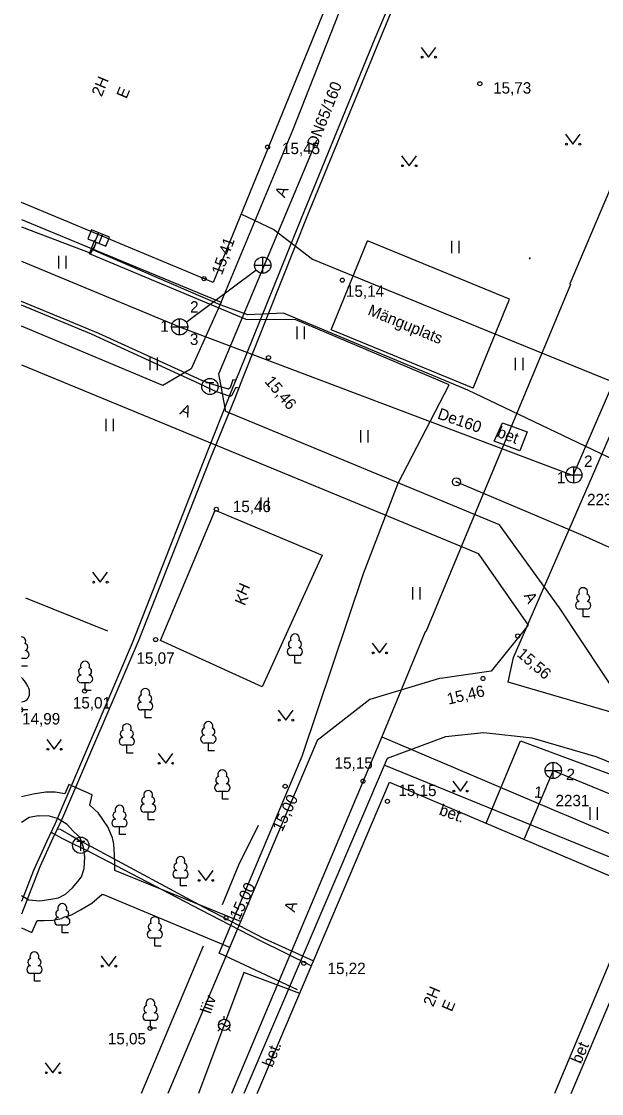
# Model space of a CAD drawing. Extents: x 713497 to 713863, y 6590062 to 6590327.
# Drawn here: x 713496.9 to 713532.5, y 6590062.3 to 6590128.2 of the extents above; entities that cross this region are included whole.
import ezdxf

# ---------------------------------------------------------------- set-up
doc = ezdxf.new("R2010")
doc.units = 0
for name, color, linetype in [('HALJASTUS', 7, 'Continuous'), ('HOONE', 7, 'Continuous'), ('HOONEDET', 7, 'Continuous'), ('KKAEV', 7, 'Continuous'), ('KORGUS', 7, 'Continuous'), ('KTRASS', 7, 'Continuous'), ('MPKAABEL', 7, 'Continuous'), ('POST', 7, 'Continuous'), ('PUU', 7, 'Continuous'), ('RAJATIS', 7, 'Continuous'), ('SIKAEV', 7, 'Continuous'), ('SITRASS', 7, 'Continuous'), ('TEE', 7, 'Continuous'), ('TKAEV', 7, 'Continuous'), ('TORU NR', 7, 'Continuous'), ('TTRASS', 7, 'Continuous'), ('VTRASS', 7, 'Continuous'), ('По умолчанию', 7, 'Continuous'), ('Слой 1', 7, 'Continuous')]:
    doc.layers.add(name, color=color, linetype=linetype)

msp = doc.modelspace()

# ---------------------------------------------------------------- linework, layer by layer
at = {"layer": 'HALJASTUS'}
for p, q in [((713521.427, 6590126.597), (713521.89, 6590125.99)), ((713521.89, 6590125.99), (713522.336, 6590126.597)), ((713530.297, 6590121.257), (713530.76, 6590120.65)), ((713530.76, 6590120.65), (713531.206, 6590121.257)), ((713520.227, 6590119.927), (713520.69, 6590119.32)), ((713520.69, 6590119.32), (713521.136, 6590119.927)), ((713515.892, 6590109.239), (713518.13, 6590114.698)), ((713526.87, 6590111.116), (713518.13, 6590114.698)), ((713523.303, 6590114.703), (713523.303, 6590113.941)), ((713523.758, 6590114.703), (713523.758, 6590113.941)), ((713499.135, 6590113.775), (713499.135, 6590113.014)), ((713499.59, 6590113.775), (713499.59, 6590113.014)), ((713524.632, 6590105.656), (713526.87, 6590111.116)), ((713513.782, 6590109.432), (713513.782, 6590108.671)), ((713514.237, 6590109.432), (713514.237, 6590108.671)), ((713524.632, 6590105.656), (713515.892, 6590109.239)), ((713504.75, 6590107.529), (713504.75, 6590106.768)), ((713505.205, 6590107.529), (713505.205, 6590106.768)), ((713527.217, 6590107.518), (713527.217, 6590106.757)), ((713527.672, 6590107.518), (713527.672, 6590106.757)), ((713502.049, 6590103.766), (713502.049, 6590103.005)), ((713502.504, 6590103.766), (713502.504, 6590103.005)), ((713517.696, 6590103.077), (713517.696, 6590102.316)), ((713518.151, 6590103.077), (713518.151, 6590102.316)), ((713511.57, 6590098.935), (713511.57, 6590098.174)), ((713512.025, 6590098.935), (713512.025, 6590098.174)), ((713501.237, 6590094.337), (713501.7, 6590093.73)), ((713501.7, 6590093.73), (713502.146, 6590094.337)), ((713520.895, 6590093.421), (713520.895, 6590092.66)), ((713521.35, 6590093.421), (713521.35, 6590092.66)), ((713518.417, 6590089.987), (713518.88, 6590089.38)), ((713518.88, 6590089.38), (713519.326, 6590089.987)), ((713512.647, 6590085.857), (713513.11, 6590085.25)), ((713513.11, 6590085.25), (713513.556, 6590085.857)), ((713498.417, 6590084.067), (713498.88, 6590083.46)), ((713498.88, 6590083.46), (713499.326, 6590084.067)), ((713505.267, 6590083.207), (713505.73, 6590082.6)), ((713505.73, 6590082.6), (713506.176, 6590083.207)), ((713523.377, 6590081.497), (713523.84, 6590080.89)), ((713523.84, 6590080.89), (713524.286, 6590081.497)), ((713531.803, 6590079.894), (713531.803, 6590079.133)), ((713532.258, 6590079.894), (713532.258, 6590079.133)), ((713507.727, 6590076.007), (713508.19, 6590075.4)), ((713508.19, 6590075.4), (713508.636, 6590076.007)), ((713501.767, 6590070.737), (713502.23, 6590070.13)), ((713502.23, 6590070.13), (713502.676, 6590070.737)), ((713498.327, 6590064.187), (713498.79, 6590063.58)), ((713498.79, 6590063.58), (713499.236, 6590064.187))]:
    msp.add_line(p, q, dxfattribs=at)
for points in [[(713502.18, 6590090.72), (713497.13, 6590092.75)], [(713511.42, 6590078.77), (713510.2, 6590076.33), (713509.2, 6590073.9)], [(713508.03, 6590071.37), (713504.228, 6590062.302)]]:
    msp.add_lwpolyline(points, dxfattribs=at)
for centre in [(713521.489, 6590125.99), (713522.318, 6590125.99), (713530.359, 6590120.65), (713531.188, 6590120.65), (713520.289, 6590119.32), (713521.118, 6590119.32), (713501.299, 6590093.73), (713502.128, 6590093.73), (713518.479, 6590089.38), (713519.308, 6590089.38), (713512.709, 6590085.25), (713513.538, 6590085.25), (713498.479, 6590083.46), (713499.308, 6590083.46), (713505.329, 6590082.6), (713506.158, 6590082.6), (713523.439, 6590080.89), (713524.268, 6590080.89), (713507.789, 6590075.4), (713508.618, 6590075.4), (713501.829, 6590070.13), (713502.658, 6590070.13), (713498.389, 6590063.58), (713499.218, 6590063.58)]:
    msp.add_circle(centre, 0.055, dxfattribs=at)
at = {"layer": 'HOONE'}
for p, q in [((713509.32, 6590066.87), (713509.32, 6590067.067)), ((713508.97, 6590066.518), (713509.181, 6590066.624)), ((713509.181, 6590066.624), (713509.459, 6590066.416)), ((713509.459, 6590066.416), (713509.67, 6590066.522)), ((713509.073, 6590066.273), (713508.933, 6590066.133)), ((713509.567, 6590066.273), (713509.707, 6590066.133))]:
    msp.add_line(p, q, dxfattribs=at)
for points in [[(713496.861, 6590174.047), (713502.16, 6590187.13), (713514.75, 6590181.98), (713510.98, 6590172.53), (713523.55, 6590167.23), (713525.32, 6590171.2), (713531.72, 6590168.66), (713508.647, 6590112.152)], [(713508.647, 6590112.152), (713496.861, 6590117.059)], [(713505.409, 6590090.144), (713508.778, 6590098.156), (713515.348, 6590095.393), (713511.649, 6590087.294), (713505.409, 6590090.144)], [(713511.353, 6590062.302), (713519.48, 6590081.443)], [(713519.48, 6590081.443), (713534.925, 6590074.886)], [(713534.925, 6590074.886), (713529.622, 6590062.302)], [(713513.966, 6590068.455), (713510.53, 6590069.75), (713507.737, 6590062.302)]]:
    msp.add_lwpolyline(points, dxfattribs=at)
msp.add_circle((713509.32, 6590066.52), 0.35, dxfattribs=at)
at = {"layer": 'HOONEDET'}
for points in [[(713496.861, 6590116.025), (713509.142, 6590110.933), (713513.543, 6590121.504), (713522.13, 6590143.33), (713524.66, 6590149.46), (713528.88, 6590159.51)], [(713530.649, 6590062.302), (713536.256, 6590075.51), (713519.161, 6590082.484)]]:
    msp.add_lwpolyline(points, dxfattribs=at)
at = {"layer": 'KKAEV'}
for p, q in [((713511.192, 6590113.21), (713512.192, 6590113.21)), ((713511.692, 6590112.71), (713511.692, 6590113.71)), ((713506.585, 6590108.92), (713506.585, 6590109.92)), ((713506.085, 6590109.42), (713507.085, 6590109.42)), ((713530.817, 6590099.818), (713530.817, 6590100.818)), ((713530.317, 6590100.318), (713531.317, 6590100.318)), ((713529.55, 6590081.656), (713529.55, 6590082.656)), ((713529.05, 6590082.156), (713530.05, 6590082.156))]:
    msp.add_line(p, q, dxfattribs=at)
for centre in [(713511.692, 6590113.21), (713506.585, 6590109.42), (713530.817, 6590100.318), (713529.55, 6590082.156)]:
    msp.add_circle(centre, 0.5, dxfattribs=at)
at = {"layer": 'KORGUS'}
for centre in [(713525.04, 6590124.36), (713511.99, 6590120.47), (713508.09, 6590112.38), (713516.58, 6590112.29), (713512.05, 6590107.53), (713508.84, 6590098.21), (713505.11, 6590090.2), (713527.37, 6590090.42), (713525.23, 6590087.81), (713500.74, 6590087.04), (713517.86, 6590081.5), (713513.07, 6590081.19), (713519.36, 6590080.26), (713509.43, 6590073.1), (713514.22, 6590070.3), (713504.77, 6590066.31)]:
    msp.add_circle(centre, 0.125, dxfattribs=at)
msp.add_arc((713496.84, 6590085.88), 0.125, 279.81452, 80.18548, dxfattribs=at)
at = {"layer": 'KTRASS'}
for p, q in [((713530.784, 6590100.288), (713536.778, 6590114.202)), ((713496.861, 6590113.464), (713506.585, 6590109.42)), ((713506.99, 6590109.712), (713511.272, 6590112.906)), ((713506.585, 6590109.42), (713530.784, 6590100.288))]:
    msp.add_line(p, q, dxfattribs=at)
for points in [[(713529.55, 6590082.156), (713527.773, 6590077.948)], [(713529.55, 6590082.156), (713542.997, 6590076.628)]]:
    msp.add_lwpolyline(points, dxfattribs=at)
at = {"layer": 'MPKAABEL'}
for points in [[(713496.861, 6590115.562), (713501.13, 6590113.94), (713501.472, 6590114.611)], [(713513.833, 6590068.67), (713509.018, 6590070.924), (713514.127, 6590083.042), (713517.884, 6590094.268), (713520.016, 6590099.81), (713523.148, 6590105.848), (713513.719, 6590109.842), (713510.668, 6590109.872), (713501.048, 6590113.897), (713501.37, 6590114.768)], [(713547.08, 6590094.66), (713531.975, 6590101.853), (713524.296, 6590105.519), (713512.967, 6590110.257), (713510.774, 6590110.16), (713509.074, 6590110.777), (713501.28, 6590114.132), (713501.453, 6590114.618)], [(713523.601, 6590099.894), (713531.341, 6590096.625), (713548.16, 6590089.06), (713554.53, 6590086.83), (713553.22, 6590083.602)]]:
    msp.add_lwpolyline(points, dxfattribs=at)
at = {"layer": 'POST'}
for p, q in [((713501.172, 6590115.383), (713500.942, 6590114.832)), ((713502.275, 6590114.922), (713501.172, 6590115.383)), ((713501.598, 6590115.205), (713501.368, 6590114.654)), ((713500.942, 6590114.832), (713502.044, 6590114.371)), ((713501.849, 6590115.1), (713501.619, 6590114.549)), ((713502.044, 6590114.371), (713502.275, 6590114.922))]:
    msp.add_line(p, q, dxfattribs=at)
for radius in [0.25, 0.0234]:
    msp.add_circle((713523.601, 6590099.894), radius, dxfattribs=at)
at = {"layer": 'PUU'}
for p, q in [((713531.63, 6590092.065), (713531.15, 6590092.065)), ((713531.39, 6590091.59), (713531.39, 6590092.065)), ((713531.77, 6590091.59), (713531.39, 6590091.59)), ((713497.09, 6590089.045), (713496.861, 6590089.045)), ((713513.91, 6590089.225), (713513.43, 6590089.225)), ((713513.67, 6590088.75), (713513.67, 6590089.225)), ((713497.23, 6590088.57), (713496.861, 6590088.57)), ((713514.05, 6590088.75), (713513.67, 6590088.75)), ((713501.01, 6590087.545), (713500.53, 6590087.545)), ((713500.77, 6590087.07), (713500.77, 6590087.545)), ((713501.15, 6590087.07), (713500.77, 6590087.07)), ((713497.26, 6590085.88), (713496.86, 6590085.88)), ((713504.71, 6590085.875), (713504.23, 6590085.875)), ((713504.47, 6590085.4), (713504.47, 6590085.875)), ((713504.85, 6590085.4), (713504.47, 6590085.4)), ((713503.58, 6590083.705), (713503.1, 6590083.705)), ((713503.34, 6590083.23), (713503.34, 6590083.705)), ((713508.59, 6590083.845), (713508.11, 6590083.845)), ((713508.35, 6590083.37), (713508.35, 6590083.845)), ((713503.72, 6590083.23), (713503.34, 6590083.23)), ((713508.73, 6590083.37), (713508.35, 6590083.37)), ((713509.45, 6590080.865), (713508.97, 6590080.865)), ((713509.21, 6590080.39), (713509.21, 6590080.865)), ((713509.59, 6590080.39), (713509.21, 6590080.39)), ((713504.89, 6590079.605), (713504.41, 6590079.605)), ((713504.65, 6590079.13), (713504.65, 6590079.605)), ((713505.03, 6590079.13), (713504.65, 6590079.13)), ((713503.13, 6590078.695), (713502.65, 6590078.695)), ((713502.89, 6590078.22), (713502.89, 6590078.695)), ((713503.27, 6590078.22), (713502.89, 6590078.22)), ((713506.88, 6590075.545), (713506.4, 6590075.545)), ((713506.64, 6590075.07), (713506.64, 6590075.545)), ((713507.02, 6590075.07), (713506.64, 6590075.07)), ((713499.61, 6590072.655), (713499.13, 6590072.655)), ((713499.37, 6590072.18), (713499.37, 6590072.655)), ((713499.75, 6590072.18), (713499.37, 6590072.18)), ((713505.3, 6590071.845), (713504.82, 6590071.845)), ((713505.06, 6590071.37), (713505.06, 6590071.845)), ((713505.44, 6590071.37), (713505.06, 6590071.37)), ((713497.9, 6590069.685), (713497.42, 6590069.685)), ((713497.66, 6590069.21), (713497.66, 6590069.685)), ((713498.04, 6590069.21), (713497.66, 6590069.21)), ((713505.03, 6590066.795), (713504.55, 6590066.795)), ((713504.79, 6590066.32), (713504.79, 6590066.795)), ((713505.17, 6590066.32), (713504.79, 6590066.32))]:
    msp.add_line(p, q, dxfattribs=at)
msp.add_lwpolyline([(713497.36, 6590086.88), (713497.36, 6590087.03), (713497.35, 6590087.095), (713497.315, 6590087.225), (713497.255, 6590087.345), (713497.11, 6590087.58), (713496.95, 6590087.785), (713496.86, 6590087.88)], dxfattribs=at)
for centre, radius, start, end in [((713531.22, 6590092.763), 0.233, 109.02174, 253.14154), ((713531.39, 6590093.11), 0.277, 332.5799, 207.4201), ((713531.56, 6590092.763), 0.233, 286.85082, 70.98591), ((713531.153, 6590092.302), 0.238, 90.0016, 269.3953), ((713531.627, 6590092.302), 0.238, 270.6047, 89.9984), ((713496.85, 6590090.09), 0.277, 332.5799, 87.66023), ((713513.5, 6590089.923), 0.233, 109.02174, 253.14154), ((713513.67, 6590090.27), 0.277, 332.5799, 207.4201), ((713513.84, 6590089.923), 0.233, 286.85082, 70.98591), ((713497.02, 6590089.743), 0.233, 286.85082, 70.98591), ((713497.087, 6590089.282), 0.238, 270.6047, 89.9984), ((713513.433, 6590089.462), 0.238, 90.0016, 269.3953), ((713513.907, 6590089.462), 0.238, 270.6047, 89.9984), ((713500.77, 6590088.59), 0.277, 332.5799, 207.4201), ((713500.6, 6590088.243), 0.233, 109.02174, 253.14154), ((713500.94, 6590088.243), 0.233, 286.85082, 70.98591), ((713500.533, 6590087.782), 0.238, 90.0016, 269.3953), ((713501.007, 6590087.782), 0.238, 270.6047, 89.9984), ((713496.86, 6590086.88), 0.5, 270.14982, 0), ((713504.47, 6590086.92), 0.277, 332.5799, 207.4201), ((713504.233, 6590086.112), 0.238, 90.0016, 269.3953), ((713504.3, 6590086.573), 0.233, 109.02174, 253.14154), ((713504.64, 6590086.573), 0.233, 286.85082, 70.98591), ((713504.707, 6590086.112), 0.238, 270.6047, 89.9984), ((713503.34, 6590084.75), 0.277, 332.5799, 207.4201), ((713508.35, 6590084.89), 0.277, 332.5799, 207.4201), ((713503.17, 6590084.403), 0.233, 109.02174, 253.14154), ((713503.51, 6590084.403), 0.233, 286.85082, 70.98591), ((713508.113, 6590084.082), 0.238, 90.0016, 269.3953), ((713508.18, 6590084.543), 0.233, 109.02174, 253.14154), ((713508.52, 6590084.543), 0.233, 286.85082, 70.98591), ((713508.587, 6590084.082), 0.238, 270.6047, 89.9984), ((713503.103, 6590083.942), 0.238, 90.0016, 269.3953), ((713503.577, 6590083.942), 0.238, 270.6047, 89.9984), ((713509.04, 6590081.563), 0.233, 109.02174, 253.14154), ((713509.21, 6590081.91), 0.277, 332.5799, 207.4201), ((713509.38, 6590081.563), 0.233, 286.85082, 70.98591), ((713504.65, 6590080.65), 0.277, 332.5799, 207.4201), ((713508.973, 6590081.102), 0.238, 90.0016, 269.3953), ((713509.447, 6590081.102), 0.238, 270.6047, 89.9984), ((713504.48, 6590080.303), 0.233, 109.02174, 253.14154), ((713504.82, 6590080.303), 0.233, 286.85082, 70.98591), ((713502.72, 6590079.393), 0.233, 109.02174, 253.14154), ((713502.89, 6590079.74), 0.277, 332.5799, 207.4201), ((713503.06, 6590079.393), 0.233, 286.85082, 70.98591), ((713504.413, 6590079.842), 0.238, 90.0016, 269.3953), ((713504.887, 6590079.842), 0.238, 270.6047, 89.9984), ((713502.653, 6590078.932), 0.238, 90.0016, 269.3953), ((713503.127, 6590078.932), 0.238, 270.6047, 89.9984), ((713506.47, 6590076.243), 0.233, 109.02174, 253.14154), ((713506.64, 6590076.59), 0.277, 332.5799, 207.4201), ((713506.81, 6590076.243), 0.233, 286.85082, 70.98591), ((713506.403, 6590075.782), 0.238, 90.0016, 269.3953), ((713506.877, 6590075.782), 0.238, 270.6047, 89.9984), ((713499.37, 6590073.7), 0.277, 332.5799, 207.4201), ((713499.133, 6590072.892), 0.238, 90.0016, 269.3953), ((713499.2, 6590073.353), 0.233, 109.02174, 253.14154), ((713499.54, 6590073.353), 0.233, 286.85082, 70.98591), ((713499.607, 6590072.892), 0.238, 270.6047, 89.9984), ((713505.06, 6590072.89), 0.277, 332.5799, 207.4201), ((713504.89, 6590072.543), 0.233, 109.02174, 253.14154), ((713505.23, 6590072.543), 0.233, 286.85082, 70.98591), ((713504.823, 6590072.082), 0.238, 90.0016, 269.3953), ((713505.297, 6590072.082), 0.238, 270.6047, 89.9984), ((713497.49, 6590070.383), 0.233, 109.02174, 253.14154), ((713497.66, 6590070.73), 0.277, 332.5799, 207.4201), ((713497.83, 6590070.383), 0.233, 286.85082, 70.98591), ((713497.423, 6590069.922), 0.238, 90.0016, 269.3953), ((713497.897, 6590069.922), 0.238, 270.6047, 89.9984), ((713504.79, 6590067.84), 0.277, 332.5799, 207.4201), ((713504.553, 6590067.032), 0.238, 90.0016, 269.3953), ((713504.62, 6590067.493), 0.233, 109.02174, 253.14154), ((713504.96, 6590067.493), 0.233, 286.85082, 70.98591), ((713505.027, 6590067.032), 0.238, 270.6047, 89.9984)]:
    msp.add_arc(centre, radius, start, end, dxfattribs=at)
at = {"layer": 'SITRASS'}
for points in [[(713520.04, 6590168.71), (713520.66, 6590170.09), (713550.09, 6590157.93), (713545.56, 6590146.97), (713536.57, 6590126.19), (713530.579, 6590112.058), (713530.622, 6590112.032), (713525.41, 6590099.54), (713521.713, 6590090.677), (713521.682, 6590090.679), (713519.02, 6590084.22), (713509.781, 6590062.302)], [(713510.396, 6590116.353), (713512.37, 6590115.41), (713514.75, 6590113.57), (713524.96, 6590109.41), (713533.116, 6590106.09), (713533.111, 6590106.069), (713537.62, 6590104.22), (713562.8, 6590094.1)], [(713519.02, 6590084.22), (713530.144, 6590079.502), (713530.341, 6590079.419), (713556.815, 6590068.191), (713567.05, 6590063.85), (713570.898, 6590062.302)]]:
    msp.add_lwpolyline(points, dxfattribs=at)
at = {"layer": 'TEE'}
for points in [[(713583.68, 6590106.09), (713587.4, 6590104.64), (713589.78, 6590103.58), (713589.96, 6590103.4), (713590.01, 6590103.08), (713590.01, 6590102.71), (713590.01, 6590102.34), (713585.33, 6590092.09), (713584.97, 6590091.18), (713584.97, 6590090.9), (713584.78, 6590090.76), (713584.05, 6590090.35), (713578.15, 6590087.01), (713571.27, 6590082.98), (713561.885, 6590077.404), (713551.992, 6590081.16), (713545.288, 6590081.565), (713534.534, 6590085.605), (713533.935, 6590086.13), (713529.929, 6590092.161), (713526.251, 6590097.247), (713509.421, 6590104.216), (713508.991, 6590106.523), (713515.019, 6590120.888)], [(713509.142, 6590110.933), (713507.297, 6590106.834), (713505.551, 6590105.821), (713496.861, 6590109.452)], [(713496.861, 6590107.09), (713516.784, 6590098.872), (713524.413, 6590095.711), (713524.94, 6590095.483), (713528.01, 6590091.097), (713525.732, 6590088.265), (713522.754, 6590087.84), (713522.553, 6590087.811), (713518.27, 6590086.509), (713515.031, 6590084.009), (713505.853, 6590062.302)], [(713527.945, 6590102.96), (713527.502, 6590101.793), (713525.922, 6590102.392), (713526.439, 6590103.53), (713527.945, 6590102.96)], [(713542.421, 6590078.847), (713532.192, 6590082.989), (713528.263, 6590084.136), (713525.285, 6590084.466), (713522.922, 6590084.219), (713519.34, 6590082.903), (713510.537, 6590062.302)], [(713510.323, 6590072.874), (713502.61, 6590076.02), (713502.61, 6590076.37), (713502.58, 6590076.95), (713502.53, 6590077.62), (713502.46, 6590078.02), (713502.17, 6590078.69), (713501.59, 6590079.53), (713501.07, 6590080.02), (713501.21, 6590080.67), (713499.77, 6590081.29), (713499.52, 6590080.73), (713498.94, 6590080.83), (713498.36, 6590080.83), (713497.59, 6590080.71), (713496.861, 6590080.533)], [(713496.861, 6590074.472), (713497.31, 6590074.21), (713497.99, 6590074.14), (713498.66, 6590074.24), (713499.14, 6590074.33), (713499.56, 6590074.56), (713500, 6590074.94), (713500.33, 6590075.33), (713500.56, 6590075.63), (713500.72, 6590076.14), (713500.75, 6590076.84), (713500.68, 6590077.44), (713500.45, 6590078.06), (713500.07, 6590078.41), (713499.68, 6590078.83), (713499.07, 6590079.2), (713498.5, 6590079.37), (713497.94, 6590079.34), (713497.91, 6590079.37), (713497.34, 6590079.27), (713496.861, 6590078.968)], [(713496.861, 6590072.482), (713497.5, 6590072.2), (713497.82, 6590072.94), (713498.26, 6590072.94), (713498.78, 6590072.96), (713499.33, 6590073.06), (713499.47, 6590073.15), (713499.93, 6590073.28), (713500.49, 6590073.59), (713501.19, 6590074), (713501.81, 6590074.54), (713501.91, 6590074.54), (713509.659, 6590071.303)]]:
    msp.add_lwpolyline(points, dxfattribs=at)
at = {"layer": 'TKAEV'}
for p, q in [((713508.197, 6590106.004), (713508.697, 6590106.004)), ((713508.447, 6590105.404), (713508.447, 6590106.004)), ((713500.257, 6590077.812), (713500.757, 6590077.812)), ((713500.507, 6590077.212), (713500.507, 6590077.812))]:
    msp.add_line(p, q, dxfattribs=at)
for centre in [(713508.447, 6590105.754), (713500.507, 6590077.562)]:
    msp.add_circle(centre, 0.5, dxfattribs=at)
at = {"layer": 'TTRASS'}
for p, q in [((713501.609, 6590109.008), (713496.861, 6590110.975)), ((713501.167, 6590108.964), (713496.861, 6590110.755)), ((713508.081, 6590105.786), (713501.167, 6590108.964)), ((713507.908, 6590106.151), (713501.609, 6590109.008)), ((713508.62, 6590105.877), (713507.908, 6590106.151)), ((713509.854, 6590106.158), (713509.698, 6590105.669)), ((713509.96, 6590106.152), (713509.854, 6590106.158)), ((713510.033, 6590106.151), (713509.96, 6590106.152)), ((713508.749, 6590105.47), (713508.081, 6590105.786)), ((713509.583, 6590105.595), (713508.62, 6590105.877)), ((713509.683, 6590105.13), (713508.749, 6590105.47)), ((713509.698, 6590105.669), (713509.583, 6590105.595)), ((713510.027, 6590105.663), (713509.795, 6590105.192)), ((713510.113, 6590105.68), (713510.027, 6590105.663)), ((713510.205, 6590105.647), (713510.113, 6590105.68)), ((713509.795, 6590105.192), (713509.683, 6590105.13))]:
    msp.add_line(p, q, dxfattribs=at)
for points in [[(713536.934, 6590171.606), (713532.46, 6590160.453), (713527.91, 6590149.36), (713523.736, 6590139.265), (713523.274, 6590138.194), (713518.578, 6590127.143), (713514.065, 6590116.073), (713510.261, 6590106.689), (713509.805, 6590105.613), (713508.03, 6590101.103), (713503.677, 6590089.984), (713498.935, 6590078.894), (713498.423, 6590077.821), (713497.604, 6590076.002), (713496.861, 6590074.102)], [(713537.097, 6590171.235), (713532.58, 6590160.187), (713527.979, 6590149.094), (713524.066, 6590139.498), (713523.58, 6590138.439), (713518.986, 6590127.351), (713514.448, 6590116.279), (713510.455, 6590106.239), (713510.003, 6590105.074), (713508.449, 6590101.266), (713504.084, 6590090.191), (713499.316, 6590079.103), (713498.784, 6590077.994), (713497.983, 6590076.242), (713496.861, 6590073.337)], [(713498.679, 6590078.357), (713498.8, 6590078.299), (713499.379, 6590077.979), (713500.091, 6590077.632), (713500.783, 6590077.305), (713507.897, 6590073.599), (713511.462, 6590071.751), (713514.683, 6590070.146)], [(713499.067, 6590078.579), (713499.245, 6590078.546), (713499.909, 6590078.163), (713500.518, 6590077.821), (713501.15, 6590077.483), (713508.067, 6590073.757), (713511.776, 6590071.824), (713514.821, 6590070.469)]]:
    msp.add_lwpolyline(points, dxfattribs=at)
at = {"layer": 'VTRASS'}
msp.add_lwpolyline([(713525.426, 6590078.919), (713527.54, 6590083.97), (713550.403, 6590075.499)], dxfattribs=at)
at = {"layer": 'По умолчанию'}
msp.add_line((713528.088, 6590113.585), (713528.156, 6590113.677), dxfattribs=at)
at = {"layer": 'Слой 1'}
msp.add_lwpolyline([(713526.78, 6590087.58), (713527.11, 6590089.1), (713547.08, 6590135.04), (713594.62, 6590115.14), (713578.96, 6590073.5), (713549.09, 6590081.07)], close=True, dxfattribs=at)

# ---------------------------------------------------------------- texts
at = {"layer": 'HOONE'}
for s, rotation, p in [('2H', 67.39526, (713501.789, 6590123.517)), ('E', 67.39526, (713503.316, 6590123.396)), ('H', 66.22905, (713510.664, 6590092.858)), ('K', 66.56177, (713510.585, 6590092.238)), ('2H', 66.87699, (713522.169, 6590067.592)), ('E', 66.87699, (713523.308, 6590067.288))]:
    msp.add_text(s, height=0.7, rotation=rotation, dxfattribs=at).set_placement(p)
at = {"layer": 'HOONEDET'}
for rotation, p in [(339.23795, (713526.04, 6590102.68)), (67.00208, (713531.252, 6590064.089))]:
    msp.add_text('bet', height=0.7, rotation=rotation, dxfattribs=at).set_placement(p)
at = {"layer": 'KORGUS'}
for s, p in [('15,73', (713525.856, 6590123.755)), ('15,45', (713512.878, 6590120.035)), ('15,14', (713516.808, 6590111.265)), ('15,46', (713509.855, 6590098.035)), ('15,07', (713503.933, 6590088.715)), ('15,01', (713500.022, 6590085.965)), ('14,99', (713496.901, 6590084.985)), ('15,15', (713516.113, 6590082.265)), ('15,15', (713520.033, 6590080.585)), ('15,22', (713515.678, 6590069.645)), ('15,05', (713502.173, 6590065.325))]:
    msp.add_text(s, height=0.7, dxfattribs=at).set_placement(p)
for s, rotation, p in [('15,41', 69.95368, (713509.182, 6590112.555)), ('15,46', 310.61205, (713511.774, 6590106.04)), ('15,56', 319.32296, (713527.268, 6590089.23)), ('15,46', 13.25827, (713523.111, 6590086.199)), ('15,00', 64.57515, (713512.886, 6590078.351)), ('15,00', 64.57515, (713510.256, 6590072.941))]:
    msp.add_text(s, height=0.7, rotation=rotation, dxfattribs=at).set_placement(p)
at = {"layer": 'KTRASS'}
msp.add_text('De160', height=0.7, rotation=340.84289, dxfattribs=at).set_placement((713522.386, 6590103.797))
at = {"layer": 'RAJATIS'}
msp.add_text('Mänguplats', height=0.7, rotation=337.71212, dxfattribs=at).set_placement((713518.097, 6590110.181))
at = {"layer": 'SIKAEV'}
for s, p in [('2230', (713531.63, 6590098.46)), ('2231', (713529.69, 6590079.96))]:
    msp.add_text(s, height=0.7, dxfattribs=at).set_placement(p)
at = {"layer": 'TEE'}
for s, rotation, p in [('A', 67.01894, (713513.043, 6590117.308)), ('A', 337.74253, (713506.544, 6590104.068)), ('A', 298.86155, (713527.715, 6590092.902)), ('bet.', 340.4926, (713522.483, 6590079.453)), ('A', 73.00462, (713513.653, 6590073.406)), ('liiv', 71.48909, (713508.492, 6590067.165)), ('bet.', 68.39964, (713512.282, 6590063.872))]:
    msp.add_text(s, height=0.7, rotation=rotation, dxfattribs=at).set_placement(p)
at = {"layer": 'TORU NR'}
for s, p in [('2', (713507.228, 6590110.297)), ('1', (713505.398, 6590109.118)), ('3', (713507.216, 6590108.307)), ('2', (713531.446, 6590100.812)), ('1', (713529.775, 6590099.804))]:
    msp.add_text(s, height=0.7, dxfattribs=at).set_placement(p)
for s, p in [('2', (713530.321, 6590081.59)), ('1', (713528.351, 6590080.5))]:
    msp.add_text(s, height=0.7, rotation=354.71026, dxfattribs=at).set_placement(p)
at = {"layer": 'TTRASS'}
msp.add_text('DN65/160', height=0.7, rotation=68.42882, dxfattribs=at).set_placement((713515.028, 6590120.393))

doc.saveas('drawing.dxf')
